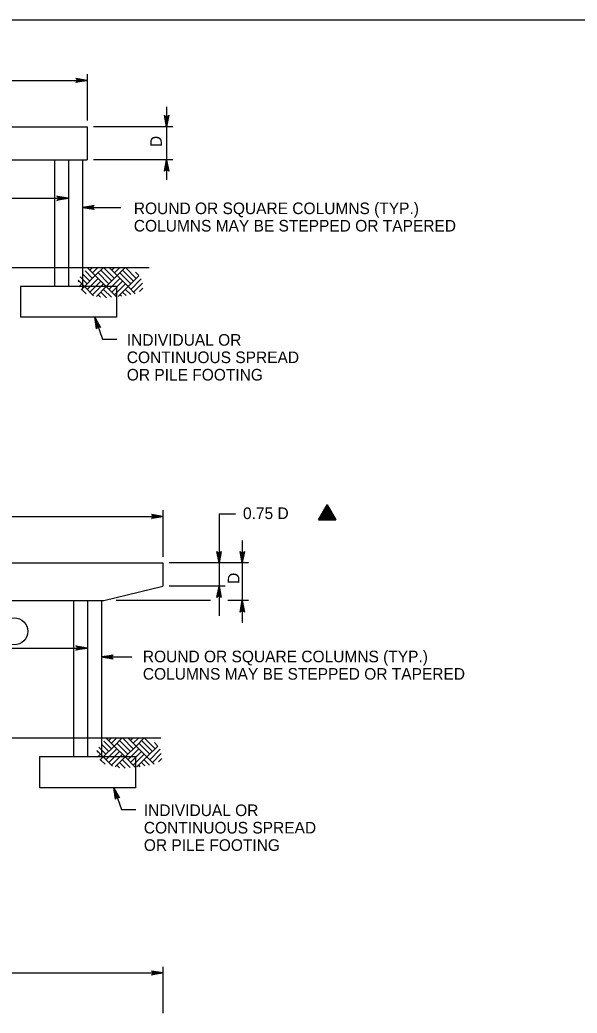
# Model space of a CAD drawing. Extents: x 646165 to 651486, y 296916 to 299292.
# Drawn here: x 648253.5 to 648397.7, y 298426.4 to 298683.3 of the extents above; entities that cross this region are included whole.
import ezdxf

# ---------------------------------------------------------------- set-up
doc = ezdxf.new("R2010")
doc.units = 0
for name, color, linetype in [('2', 7, 'Continuous'), ('34', 7, 'Continuous'), ('50', 7, 'Continuous'), ('51', 7, 'Continuous'), ('52', 7, 'Continuous'), ('53', 7, 'Continuous'), ('56', 7, 'Continuous')]:
    doc.layers.add(name, color=color, linetype=linetype)

msp = doc.modelspace()

# ---------------------------------------------------------------- linework, layer by layer
at = {"layer": '2'}
msp.add_line((648147.59, 298683.25), (648933.59, 298683.25), dxfattribs=at)
at = {"layer": '34'}
for p, q in [((648161.03, 298619.2), (648286.97, 298619.2)), ((648157.63, 298497.55), (648290.01, 298497.55))]:
    msp.add_line(p, q, dxfattribs=at)
at = {"layer": '50'}
for p, q in [((648266.11, 298647.07), (648266.11, 298614.32)), ((648271.03, 298533.05), (648271.03, 298492.67))]:
    msp.add_line(p, q, dxfattribs=at)
at = {"layer": '51'}
for p, q in [((648193.01, 298655.59), (648270.96, 298655.59)), ((648270.96, 298655.59), (648270.96, 298647.07)), ((648193.01, 298647.07), (648270.96, 298647.07)), ((648262.45, 298647.07), (648262.45, 298614.32)), ((648269.76, 298647.07), (648269.76, 298613.81)), ((648253.71, 298614.32), (648253.71, 298606.32)), ((648278.51, 298614.32), (648253.71, 298614.32)), ((648278.51, 298614.32), (648278.51, 298606.32)), ((648278.51, 298606.32), (648253.71, 298606.32)), ((648173.42, 298542.81), (648290.55, 298542.81)), ((648290.55, 298542.81), (648290.55, 298536.81)), ((648275.28, 298533.05), (648290.55, 298536.81)), ((648188.69, 298533.05), (648275.28, 298533.05)), ((648267.37, 298533.05), (648267.37, 298492.67)), ((648274.68, 298533.05), (648274.68, 298492.67)), ((648258.63, 298492.67), (648258.63, 298484.67)), ((648283.43, 298492.67), (648258.63, 298492.67)), ((648283.43, 298492.67), (648283.43, 298484.67)), ((648283.43, 298484.67), (648258.63, 298484.67))]:
    msp.add_line(p, q, dxfattribs=at)
at = {"layer": '52'}
for p, q in [((648270.96, 298669.19), (648270.96, 298657.19)), ((648193.01, 298667.59), (648270.96, 298667.59)), ((648291.5, 298660.74), (648291.5, 298641.92)), ((648293.1, 298655.59), (648272.56, 298655.59)), ((648293.1, 298647.07), (648272.56, 298647.07)), ((648197.86, 298637.13), (648266.11, 298637.13)), ((648290.55, 298556.41), (648290.55, 298544.41)), ((648305.08, 298555.53), (648305.08, 298529.14)), ((648305.08, 298555.53), (648309.37, 298555.53)), ((648173.42, 298554.81), (648290.55, 298554.81)), ((648311.08, 298548.63), (648311.08, 298527.28)), ((648312.68, 298542.81), (648292.15, 298542.81)), ((648306.68, 298536.81), (648292.15, 298536.81)), ((648302.85, 298533.05), (648278.48, 298533.05)), ((648312.68, 298533.05), (648307.32, 298533.05)), ((648173.42, 298520.78), (648271.03, 298520.78)), ((648290.55, 298438.37), (648290.55, 298426.37)), ((648173.42, 298436.77), (648290.55, 298436.77))]:
    msp.add_line(p, q, dxfattribs=at)
for points in [[(648270.96, 298667.59), (648267.98, 298667.03), (648268.1, 298667.11), (648268.21, 298667.19), (648268.27, 298667.29), (648268.33, 298667.39), (648268.35, 298667.49), (648268.36, 298667.59), (648268.35, 298667.69), (648268.33, 298667.79), (648268.27, 298667.89), (648268.21, 298667.99), (648268.1, 298668.07), (648267.98, 298668.15), (648270.96, 298667.59), (648268.1, 298668.07), (648268.21, 298667.99), (648270.96, 298667.59), (648268.27, 298667.89), (648268.33, 298667.79), (648270.96, 298667.59), (648268.35, 298667.69), (648268.36, 298667.59), (648270.96, 298667.59), (648268.35, 298667.49), (648268.33, 298667.39), (648270.96, 298667.59), (648268.27, 298667.29), (648268.21, 298667.19), (648270.96, 298667.59), (648268.1, 298667.11)], [(648291.5, 298655.59), (648290.94, 298658.57), (648291.02, 298658.45), (648291.1, 298658.34), (648291.2, 298658.28), (648291.3, 298658.22), (648291.4, 298658.2), (648291.5, 298658.19), (648291.6, 298658.2), (648291.7, 298658.22), (648291.8, 298658.28), (648291.9, 298658.34), (648291.98, 298658.45), (648292.06, 298658.57), (648291.5, 298655.59), (648291.98, 298658.45), (648291.9, 298658.34), (648291.5, 298655.59), (648291.8, 298658.28), (648291.7, 298658.22), (648291.5, 298655.59), (648291.6, 298658.2), (648291.5, 298658.19), (648291.5, 298655.59), (648291.4, 298658.2), (648291.3, 298658.22), (648291.5, 298655.59), (648291.2, 298658.28), (648291.1, 298658.34), (648291.5, 298655.59), (648291.02, 298658.45)], [(648291.5, 298647.07), (648292.06, 298644.08), (648291.98, 298644.2), (648291.9, 298644.31), (648291.8, 298644.37), (648291.7, 298644.43), (648291.6, 298644.45), (648291.5, 298644.47), (648291.4, 298644.45), (648291.3, 298644.43), (648291.2, 298644.37), (648291.1, 298644.31), (648291.02, 298644.2), (648290.94, 298644.08), (648291.5, 298647.07), (648291.02, 298644.2), (648291.1, 298644.31), (648291.5, 298647.07), (648291.2, 298644.37), (648291.3, 298644.43), (648291.5, 298647.07), (648291.4, 298644.45), (648291.5, 298644.47), (648291.5, 298647.07), (648291.6, 298644.45), (648291.7, 298644.43), (648291.5, 298647.07), (648291.8, 298644.37), (648291.9, 298644.31), (648291.5, 298647.07), (648291.98, 298644.2)], [(648266.11, 298637.13), (648263.13, 298636.57), (648263.24, 298636.65), (648263.36, 298636.73), (648263.42, 298636.83), (648263.47, 298636.93), (648263.49, 298637.03), (648263.51, 298637.13), (648263.49, 298637.23), (648263.47, 298637.33), (648263.42, 298637.43), (648263.36, 298637.53), (648263.24, 298637.61), (648263.13, 298637.68), (648266.11, 298637.13), (648263.24, 298637.61), (648263.36, 298637.53), (648266.11, 298637.13), (648263.42, 298637.43), (648263.47, 298637.33), (648266.11, 298637.13), (648263.49, 298637.23), (648263.51, 298637.13), (648266.11, 298637.13), (648263.49, 298637.03), (648263.47, 298636.93), (648266.11, 298637.13), (648263.42, 298636.83), (648263.36, 298636.73), (648266.11, 298637.13), (648263.24, 298636.65)], [(648269.76, 298634.74), (648272.75, 298635.3), (648272.63, 298635.22), (648272.52, 298635.14), (648272.46, 298635.04), (648272.4, 298634.94), (648272.38, 298634.84), (648272.36, 298634.74), (648272.38, 298634.64), (648272.4, 298634.54), (648272.46, 298634.44), (648272.52, 298634.34), (648272.63, 298634.26), (648272.75, 298634.18), (648269.76, 298634.74), (648272.63, 298634.26), (648272.52, 298634.34), (648269.76, 298634.74), (648272.46, 298634.44), (648272.4, 298634.54), (648269.76, 298634.74), (648272.38, 298634.64), (648272.36, 298634.74), (648269.76, 298634.74), (648272.38, 298634.84), (648272.4, 298634.94), (648269.76, 298634.74), (648272.46, 298635.04), (648272.52, 298635.14), (648269.76, 298634.74), (648272.63, 298635.22)], [(648269.76, 298634.74), (648279.62, 298634.74)], [(648272.89, 298606.32), (648274.93, 298600.68), (648278.64, 298600.68)], [(648272.89, 298606.32), (648274.43, 298603.71), (648274.32, 298603.79), (648274.2, 298603.87), (648274.09, 298603.89), (648273.97, 298603.91), (648273.87, 298603.89), (648273.77, 298603.88), (648273.69, 298603.83), (648273.6, 298603.78), (648273.52, 298603.69), (648273.45, 298603.6), (648273.41, 298603.46), (648273.38, 298603.33), (648272.89, 298606.32), (648273.41, 298603.46), (648273.45, 298603.6), (648272.89, 298606.32), (648273.52, 298603.69), (648273.6, 298603.78), (648272.89, 298606.32), (648273.69, 298603.83), (648273.77, 298603.88), (648272.89, 298606.32), (648273.87, 298603.89), (648273.97, 298603.91), (648272.89, 298606.32), (648274.09, 298603.89), (648274.2, 298603.87), (648272.89, 298606.32), (648274.32, 298603.79)], [(648290.55, 298554.81), (648287.56, 298554.25), (648287.68, 298554.33), (648287.79, 298554.41), (648287.85, 298554.51), (648287.91, 298554.61), (648287.93, 298554.71), (648287.95, 298554.81), (648287.93, 298554.91), (648287.91, 298555.01), (648287.85, 298555.11), (648287.79, 298555.21), (648287.68, 298555.29), (648287.56, 298555.37), (648290.55, 298554.81), (648287.68, 298555.29), (648287.79, 298555.21), (648290.55, 298554.81), (648287.85, 298555.11), (648287.91, 298555.01), (648290.55, 298554.81), (648287.93, 298554.91), (648287.95, 298554.81), (648290.55, 298554.81), (648287.93, 298554.71), (648287.91, 298554.61), (648290.55, 298554.81), (648287.85, 298554.51), (648287.79, 298554.41), (648290.55, 298554.81), (648287.68, 298554.33)], [(648305.08, 298542.81), (648304.52, 298545.8), (648304.6, 298545.68), (648304.68, 298545.57), (648304.78, 298545.51), (648304.88, 298545.45), (648304.98, 298545.43), (648305.08, 298545.41), (648305.18, 298545.43), (648305.28, 298545.45), (648305.38, 298545.51), (648305.48, 298545.57), (648305.56, 298545.68), (648305.64, 298545.8), (648305.08, 298542.81), (648305.56, 298545.68), (648305.48, 298545.57), (648305.08, 298542.81), (648305.38, 298545.51), (648305.28, 298545.45), (648305.08, 298542.81), (648305.18, 298545.43), (648305.08, 298545.41), (648305.08, 298542.81), (648304.98, 298545.43), (648304.88, 298545.45), (648305.08, 298542.81), (648304.78, 298545.51), (648304.68, 298545.57), (648305.08, 298542.81), (648304.6, 298545.68)], [(648311.08, 298542.81), (648310.52, 298545.8), (648310.6, 298545.68), (648310.68, 298545.57), (648310.78, 298545.51), (648310.88, 298545.45), (648310.98, 298545.43), (648311.08, 298545.41), (648311.18, 298545.43), (648311.28, 298545.45), (648311.38, 298545.51), (648311.48, 298545.57), (648311.56, 298545.68), (648311.64, 298545.8), (648311.08, 298542.81), (648311.56, 298545.68), (648311.48, 298545.57), (648311.08, 298542.81), (648311.38, 298545.51), (648311.28, 298545.45), (648311.08, 298542.81), (648311.18, 298545.43), (648311.08, 298545.41), (648311.08, 298542.81), (648310.98, 298545.43), (648310.88, 298545.45), (648311.08, 298542.81), (648310.78, 298545.51), (648310.68, 298545.57), (648311.08, 298542.81), (648310.6, 298545.68)], [(648305.08, 298536.81), (648305.64, 298533.83), (648305.56, 298533.95), (648305.48, 298534.06), (648305.38, 298534.12), (648305.28, 298534.18), (648305.18, 298534.2), (648305.08, 298534.21), (648304.98, 298534.2), (648304.88, 298534.18), (648304.78, 298534.12), (648304.68, 298534.06), (648304.6, 298533.95), (648304.52, 298533.83), (648305.08, 298536.81), (648304.6, 298533.95), (648304.68, 298534.06), (648305.08, 298536.81), (648304.78, 298534.12), (648304.88, 298534.18), (648305.08, 298536.81), (648304.98, 298534.2), (648305.08, 298534.21), (648305.08, 298536.81), (648305.18, 298534.2), (648305.28, 298534.18), (648305.08, 298536.81), (648305.38, 298534.12), (648305.48, 298534.06), (648305.08, 298536.81), (648305.56, 298533.95)], [(648311.08, 298533.05), (648311.64, 298530.07), (648311.56, 298530.19), (648311.48, 298530.3), (648311.38, 298530.36), (648311.28, 298530.42), (648311.18, 298530.44), (648311.08, 298530.45), (648310.98, 298530.44), (648310.88, 298530.42), (648310.78, 298530.36), (648310.68, 298530.3), (648310.6, 298530.19), (648310.52, 298530.07), (648311.08, 298533.05), (648310.6, 298530.19), (648310.68, 298530.3), (648311.08, 298533.05), (648310.78, 298530.36), (648310.88, 298530.42), (648311.08, 298533.05), (648310.98, 298530.44), (648311.08, 298530.45), (648311.08, 298533.05), (648311.18, 298530.44), (648311.28, 298530.42), (648311.08, 298533.05), (648311.38, 298530.36), (648311.48, 298530.3), (648311.08, 298533.05), (648311.56, 298530.19)], [(648271.03, 298520.78), (648268.04, 298520.22), (648268.16, 298520.3), (648268.27, 298520.38), (648268.33, 298520.48), (648268.39, 298520.58), (648268.41, 298520.68), (648268.43, 298520.78), (648268.41, 298520.88), (648268.39, 298520.98), (648268.33, 298521.08), (648268.27, 298521.18), (648268.16, 298521.26), (648268.04, 298521.33), (648271.03, 298520.78), (648268.16, 298521.26), (648268.27, 298521.18), (648271.03, 298520.78), (648268.33, 298521.08), (648268.39, 298520.98), (648271.03, 298520.78), (648268.41, 298520.88), (648268.43, 298520.78), (648271.03, 298520.78), (648268.41, 298520.68), (648268.39, 298520.58), (648271.03, 298520.78), (648268.33, 298520.48), (648268.27, 298520.38), (648271.03, 298520.78), (648268.16, 298520.3)], [(648274.68, 298518.48), (648277.66, 298519.04), (648277.55, 298518.96), (648277.43, 298518.88), (648277.37, 298518.78), (648277.32, 298518.68), (648277.3, 298518.58), (648277.28, 298518.48), (648277.3, 298518.38), (648277.32, 298518.28), (648277.37, 298518.18), (648277.43, 298518.08), (648277.55, 298518), (648277.66, 298517.92), (648274.68, 298518.48), (648277.55, 298518), (648277.43, 298518.08), (648274.68, 298518.48), (648277.37, 298518.18), (648277.32, 298518.28), (648274.68, 298518.48), (648277.3, 298518.38), (648277.28, 298518.48), (648274.68, 298518.48), (648277.3, 298518.58), (648277.32, 298518.68), (648274.68, 298518.48), (648277.37, 298518.78), (648277.43, 298518.88), (648274.68, 298518.48), (648277.55, 298518.96)], [(648274.68, 298518.48), (648282.53, 298518.48)], [(648277.81, 298484.67), (648279.84, 298479.03), (648283.55, 298479.03)], [(648277.81, 298484.67), (648279.35, 298482.06), (648279.23, 298482.14), (648279.12, 298482.22), (648279, 298482.24), (648278.89, 298482.26), (648278.79, 298482.24), (648278.69, 298482.23), (648278.6, 298482.18), (648278.51, 298482.13), (648278.44, 298482.04), (648278.37, 298481.95), (648278.33, 298481.81), (648278.29, 298481.68), (648277.81, 298484.67), (648278.33, 298481.81), (648278.37, 298481.95), (648277.81, 298484.67), (648278.44, 298482.04), (648278.51, 298482.13), (648277.81, 298484.67), (648278.6, 298482.18), (648278.69, 298482.23), (648277.81, 298484.67), (648278.79, 298482.24), (648278.89, 298482.26), (648277.81, 298484.67), (648279, 298482.24), (648279.12, 298482.22), (648277.81, 298484.67), (648279.23, 298482.14)], [(648290.55, 298436.77), (648287.56, 298436.21), (648287.68, 298436.29), (648287.79, 298436.37), (648287.85, 298436.47), (648287.91, 298436.57), (648287.93, 298436.67), (648287.95, 298436.77), (648287.93, 298436.87), (648287.91, 298436.97), (648287.85, 298437.07), (648287.79, 298437.17), (648287.68, 298437.25), (648287.56, 298437.33), (648290.55, 298436.77), (648287.68, 298437.25), (648287.79, 298437.17), (648290.55, 298436.77), (648287.85, 298437.07), (648287.91, 298436.97), (648290.55, 298436.77), (648287.93, 298436.87), (648287.95, 298436.77), (648290.55, 298436.77), (648287.93, 298436.67), (648287.91, 298436.57), (648290.55, 298436.77), (648287.85, 298436.47), (648287.79, 298436.37), (648290.55, 298436.77), (648287.68, 298436.29)]]:
    msp.add_lwpolyline(points, dxfattribs=at)
msp.add_circle((648252.06, 298525.1), 3.5, dxfattribs=at)
at = {"layer": '53'}
msp.add_line((648333.05, 298555.25), (648333.05, 298555.25), dxfattribs=at)
for points in [[(648330.82, 298553.96), (648335.28, 298553.96), (648333.05, 298557.83), (648330.82, 298553.96)], [(648330.82, 298553.96), (648333.05, 298557.83), (648335.28, 298553.96), (648330.82, 298553.96), (648333.05, 298557.71), (648335.21, 298554.02), (648330.91, 298554.01), (648333.06, 298557.6), (648335.12, 298554.07), (648331.01, 298554.06), (648333.06, 298557.48), (648335.02, 298554.14), (648331.11, 298554.11), (648333.06, 298557.37), (648334.93, 298554.19), (648331.22, 298554.18), (648333.06, 298557.23), (648334.82, 298554.25), (648331.34, 298554.25), (648333.06, 298557.09), (648334.71, 298554.31), (648331.44, 298554.31), (648333.05, 298556.96), (648334.6, 298554.38), (648331.55, 298554.37), (648333.05, 298556.83), (648334.48, 298554.45), (648331.65, 298554.43), (648333.07, 298556.71), (648334.35, 298554.51), (648331.77, 298554.5), (648333.07, 298556.58), (648334.21, 298554.6), (648331.89, 298554.56), (648333.07, 298556.43), (648334.1, 298554.68), (648332.01, 298554.62), (648333.06, 298556.3), (648333.98, 298554.75), (648332.14, 298554.69), (648333.07, 298556.17), (648333.87, 298554.81), (648332.27, 298554.75), (648333.06, 298556.02), (648333.74, 298554.88), (648332.41, 298554.82), (648333.06, 298555.89), (648333.6, 298554.95), (648332.52, 298554.89), (648333.06, 298555.76), (648333.48, 298555.02), (648332.64, 298554.95), (648333.06, 298555.64), (648333.37, 298555.07), (648332.75, 298555.01), (648333.06, 298555.51), (648333.28, 298555.13), (648332.85, 298555.06), (648333.06, 298555.39), (648333.19, 298555.17), (648332.97, 298555.14), (648333.06, 298555.25), (648335.27, 298553.98), (648333.06, 298555.25), (648333.06, 298557.8), (648333.06, 298555.24), (648330.83, 298553.97)]]:
    msp.add_lwpolyline(points, dxfattribs=at)
at = {"layer": '56'}
for p, q in [((648271.64, 298615.68), (648269.74, 298617.58)), ((648270.22, 298614.27), (648273.05, 298617.1)), ((648272.35, 298616.39), (648270.38, 298618.35)), ((648273.05, 298617.1), (648271.03, 298619.12)), ((648271.64, 298618.51), (648272.32, 298619.2)), ((648272.35, 298617.81), (648273.74, 298619.2)), ((648273.05, 298617.1), (648275.15, 298619.2)), ((648275.88, 298614.27), (648273.05, 298617.1)), ((648276.59, 298614.98), (648273.76, 298617.81)), ((648277.29, 298615.68), (648274.47, 298618.51)), ((648278, 298616.39), (648275.19, 298619.2)), ((648275.88, 298614.27), (648278.71, 298617.1)), ((648278.71, 298617.1), (648276.61, 298619.2)), ((648277.29, 298618.51), (648277.98, 298619.2)), ((648278, 298617.81), (648279.4, 298619.2)), ((648278.71, 298617.1), (648280.81, 298619.2)), ((648281.54, 298614.27), (648278.71, 298617.1)), ((648282.24, 298614.98), (648279.42, 298617.81)), ((648282.95, 298615.68), (648280.12, 298618.51)), ((648283.66, 298616.39), (648280.85, 298619.2)), ((648281.54, 298614.27), (648284.35, 298617.09)), ((648284.29, 298617.17), (648283.49, 298617.98)), ((648283.66, 298617.81), (648283.68, 298617.83)), ((648270.22, 298614.27), (648268.58, 298615.91)), ((648268.62, 298615.5), (648268.81, 298615.68)), ((648268.75, 298614.21), (648269.52, 298614.98)), ((648270.93, 298614.98), (648269.09, 298616.81)), ((648270.93, 298613.56), (648273.76, 298616.39)), ((648271.64, 298612.86), (648274.47, 298615.68)), ((648272.35, 298612.15), (648275.17, 298614.98)), ((648276.59, 298613.56), (648279.42, 298616.39)), ((648277.29, 298612.86), (648280.12, 298615.68)), ((648278, 298612.15), (648280.83, 298614.98)), ((648282.24, 298613.56), (648284.94, 298616.26)), ((648282.95, 298612.86), (648285.25, 298615.15)), ((648269.37, 298613.41), (648270.22, 298614.27)), ((648270.7, 298612.38), (648269.52, 298613.56)), ((648272.61, 298611.88), (648270.22, 298614.27)), ((648273.34, 298611.73), (648275.88, 298614.27)), ((648274.4, 298611.51), (648273.76, 298612.15)), ((648275.93, 298611.39), (648274.47, 298612.86)), ((648277.22, 298611.52), (648275.17, 298613.56)), ((648278.51, 298611.64), (648275.88, 298614.27)), ((648278.95, 298611.68), (648281.54, 298614.27)), ((648279.8, 298611.76), (648279.42, 298612.15)), ((648281.02, 298611.96), (648280.12, 298612.86)), ((648282.21, 298612.19), (648280.83, 298613.56)), ((648283.4, 298612.41), (648281.54, 298614.27)), ((648284.51, 298613), (648285.38, 298613.87)), ((648277.22, 298494.74), (648275.26, 298496.7)), ((648277.93, 298495.45), (648275.9, 298497.47)), ((648276.51, 298496.86), (648277.2, 298497.55)), ((648277.22, 298496.15), (648278.61, 298497.55)), ((648277.93, 298495.45), (648280.03, 298497.55)), ((648282.17, 298494.03), (648279.34, 298496.86)), ((648282.88, 298494.74), (648280.07, 298497.55)), ((648283.58, 298495.45), (648281.48, 298497.55)), ((648282.17, 298496.86), (648282.86, 298497.55)), ((648282.88, 298496.15), (648284.27, 298497.55)), ((648283.58, 298495.45), (648285.68, 298497.55)), ((648287.83, 298494.03), (648285, 298496.86)), ((648288.53, 298494.74), (648285.73, 298497.55)), ((648289.17, 298495.52), (648288.36, 298496.33)), ((648275.1, 298492.62), (648273.46, 298494.26)), ((648273.5, 298493.85), (648273.68, 298494.03)), ((648275.81, 298493.33), (648273.97, 298495.16)), ((648276.51, 298494.03), (648274.61, 298495.93)), ((648275.1, 298492.62), (648277.93, 298495.45)), ((648275.81, 298491.91), (648278.63, 298494.74)), ((648276.51, 298491.2), (648279.34, 298494.03)), ((648280.76, 298492.62), (648277.93, 298495.45)), ((648281.46, 298493.33), (648278.63, 298496.15)), ((648280.76, 298492.62), (648283.58, 298495.45)), ((648281.46, 298491.91), (648284.29, 298494.74)), ((648282.17, 298491.2), (648285, 298494.03)), ((648286.41, 298492.62), (648283.58, 298495.45)), ((648287.12, 298493.33), (648284.29, 298496.15)), ((648286.41, 298492.62), (648289.23, 298495.43)), ((648287.12, 298491.91), (648289.82, 298494.61)), ((648288.53, 298496.15), (648288.55, 298496.17)), ((648273.63, 298492.56), (648274.39, 298493.33)), ((648274.24, 298491.76), (648275.1, 298492.62)), ((648275.58, 298490.73), (648274.39, 298491.91)), ((648277.48, 298490.23), (648275.1, 298492.62)), ((648277.22, 298490.5), (648280.05, 298493.33)), ((648278.22, 298490.08), (648280.76, 298492.62)), ((648280.8, 298489.74), (648279.34, 298491.2)), ((648282.1, 298489.86), (648280.05, 298491.91)), ((648283.39, 298489.99), (648280.76, 298492.62)), ((648282.88, 298490.5), (648285.7, 298493.33)), ((648283.82, 298490.03), (648286.41, 298492.62)), ((648285.89, 298490.31), (648285, 298491.2)), ((648287.08, 298490.53), (648285.7, 298491.91)), ((648288.27, 298490.76), (648286.41, 298492.62)), ((648287.83, 298491.2), (648290.12, 298493.5)), ((648289.39, 298491.35), (648290.25, 298492.22)), ((648279.28, 298489.85), (648278.63, 298490.5)), ((648284.68, 298490.11), (648284.29, 298490.5))]:
    msp.add_line(p, q, dxfattribs=at)

# ---------------------------------------------------------------- texts
at = {"layer": '53'}
for p in [(648290.27, 298650.35), (648310.34, 298537.37)]:
    msp.add_text('D', height=3, rotation=90, dxfattribs=at).set_placement(p)
for s, p in [('ROUND OR SQUARE COLUMNS (TYP.)', (648283.02, 298633.01)), ('COLUMNS MAY BE STEPPED OR TAPERED', (648283.02, 298628.51)), ('INDIVIDUAL OR', (648281.2, 298598.98)), ('CONTINUOUS SPREAD', (648281.2, 298594.48)), ('OR PILE FOOTING', (648281.2, 298589.98)), ('0.75 D', (648311.27, 298554.15)), ('ROUND OR SQUARE COLUMNS (TYP.)', (648285.35, 298517.11)), ('COLUMNS MAY BE STEPPED OR TAPERED', (648285.35, 298512.61)), ('INDIVIDUAL OR', (648285.61, 298477.33)), ('CONTINUOUS SPREAD', (648285.61, 298472.83)), ('OR PILE FOOTING', (648285.61, 298468.33))]:
    msp.add_text(s, height=3, dxfattribs=at).set_placement(p)

doc.saveas('drawing.dxf')
